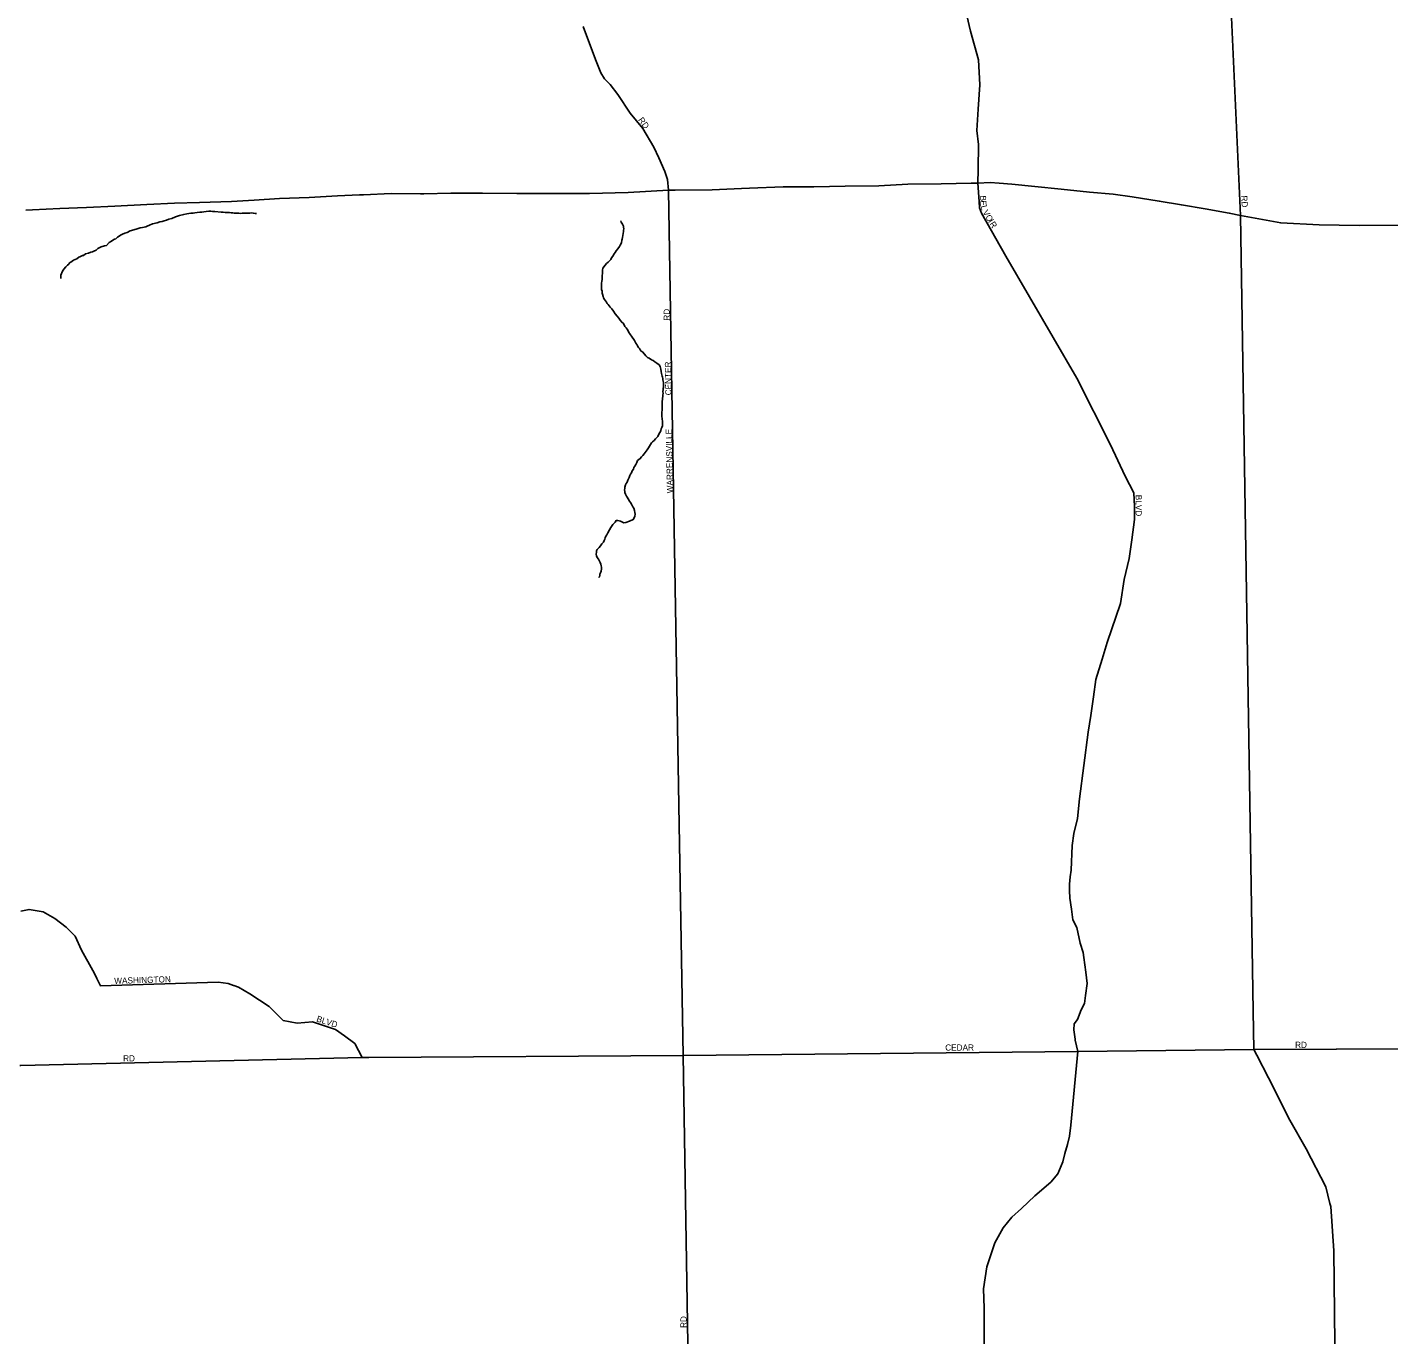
# Model space of a CAD drawing. Extents: x 2139079 to 2262683, y 1235796 to 1334992.
# Drawn here: x 2227269 to 2238345, y 1274636 to 1285350 of the extents above; entities that cross this region are included whole.
import ezdxf

# ---------------------------------------------------------------- set-up
doc = ezdxf.new("R2010")
doc.units = 0
for name, color, linetype in [('GM_X_City_Street', 7, 'Continuous'), ('GM_X_City_Street_Text', 7, 'Continuous'), ('GM_X_Minor_River', 7, 'Continuous'), ('GM_X_US_Route', 7, 'Continuous')]:
    doc.layers.add(name, color=color, linetype=linetype)

msp = doc.modelspace()

# ---------------------------------------------------------------- linework, layer by layer
at = {"layer": 'GM_X_City_Street'}
msp.add_line((2232642, 1274636), (2232605, 1276982), dxfattribs=at)
for points in [[(2237139, 1283818), (2237014, 1286565), (2236915, 1287904), (2236899, 1288052), (2236904, 1288072), (2236952, 1288095), (2237028, 1288171), (2237100, 1288250), (2237206, 1288419), (2237198, 1288487), (2237162, 1288590), (2237128, 1288654), (2237062, 1288738), (2236872, 1288918), (2236470, 1289275), (2235905, 1289793), (2235277, 1290427), (2232536, 1293112)], [(2232486, 1284023), (2232477, 1284111), (2232457, 1284177), (2232408, 1284288), (2232366, 1284375), (2232278, 1284526), (2232174, 1284651), (2232074, 1284803), (2232012, 1284884), (2231965, 1284931), (2231935, 1284980), (2231891, 1285086), (2231793, 1285356)], [(2234913, 1285445), (2234942, 1285319), (2235009, 1285084), (2235018, 1284880), (2235005, 1284683), (2234995, 1284510), (2235008, 1284396), (2235006, 1284191), (2235003, 1284081), (2235012, 1283932), (2235016, 1283880), (2235031, 1283836), (2235230, 1283488), (2235807, 1282493), (2236082, 1281952), (2236201, 1281696), (2236271, 1281562), (2236278, 1281450), (2236278, 1281343), (2236255, 1281178), (2236234, 1281027), (2236193, 1280855), (2236164, 1280660), (2236054, 1280342), (2236013, 1280206), (2235963, 1280042), (2235943, 1279901), (2235921, 1279748), (2235900, 1279613), (2235828, 1279071), (2235812, 1278912), (2235783, 1278789), (2235771, 1278692), (2235761, 1278491), (2235754, 1278437), (2235749, 1278377), (2235747, 1278326), (2235752, 1278262), (2235765, 1278172), (2235775, 1278086), (2235807, 1278023), (2235836, 1277897), (2235860, 1277819), (2235865, 1277779), (2235880, 1277661), (2235893, 1277567), (2235877, 1277471), (2235869, 1277404), (2235844, 1277353), (2235814, 1277274), (2235787, 1277241), (2235784, 1277191), (2235793, 1277116)], [(2232505, 1282876), (2232486, 1284023)], [(2237243, 1277344), (2237243, 1277344), (2237139, 1283818)], [(2232573, 1278860), (2232505, 1282876), (2232505, 1282876)], [(2232600, 1277295), (2232573, 1278860), (2232573, 1278860)], [(2227217, 1278156), (2227285, 1278171), (2227399, 1278150), (2227493, 1278098), (2227586, 1278026), (2227659, 1277953), (2227711, 1277839), (2227804, 1277673), (2227835, 1277611)], [(2227835, 1277611), (2227835, 1277610), (2227866, 1277548), (2228822, 1277579), (2228905, 1277568), (2228947, 1277552)], [(2228947, 1277552), (2228949, 1277552), (2228988, 1277537), (2229081, 1277485), (2229237, 1277381), (2229351, 1277267), (2229466, 1277246), (2229590, 1277256), (2229777, 1277194), (2229850, 1277142), (2229933, 1277080), (2229995, 1276965)], [(2232605, 1276982), (2232600, 1277295), (2232600, 1277295)], [(2237272, 1276984), (2237248, 1277030), (2237243, 1277344)], [(2235793, 1277116), (2235794, 1277112), (2235794, 1277107), (2235815, 1277015), (2235758, 1276416), (2235749, 1276325), (2235733, 1276259), (2235711, 1276184), (2235693, 1276117), (2235654, 1276019), (2235596, 1275951), (2235465, 1275840), (2235358, 1275736), (2235280, 1275666), (2235209, 1275579), (2235140, 1275458), (2235076, 1275263), (2235048, 1275082), (2235053, 1274925), (2235053, 1274711), (2235054, 1274636)], [(2237921, 1277033), (2239464, 1277041), (2239474, 1277041)], [(2227208, 1276902), (2227218, 1276902), (2229995, 1276965), (2230047, 1276966), (2230047, 1276966)], [(2230047, 1276966), (2232605, 1276982)], [(2232605, 1276982), (2235815, 1277015), (2237248, 1277030), (2237918, 1277033), (2237921, 1277033)], [(2237366, 1276799), (2237272, 1276984), (2237272, 1276984)], [(2237867, 1275777), (2237867, 1275777), (2237833, 1275912), (2237672, 1276222), (2237541, 1276456), (2237366, 1276799), (2237366, 1276799)], [(2237906, 1274636), (2237899, 1275392), (2237874, 1275752), (2237867, 1275777)]]:
    msp.add_lwpolyline(points, dxfattribs=at)
at = {"layer": 'GM_X_Minor_River'}
for points in [[(2227543, 1283304), (2227543, 1283318), (2227544, 1283333), (2227556, 1283365), (2227568, 1283381), (2227583, 1283400), (2227597, 1283414), (2227607, 1283422), (2227613, 1283432), (2227625, 1283439), (2227646, 1283453), (2227658, 1283459), (2227674, 1283466), (2227688, 1283478), (2227698, 1283482), (2227708, 1283486), (2227718, 1283491), (2227728, 1283493), (2227744, 1283505), (2227768, 1283510), (2227788, 1283520), (2227800, 1283522), (2227812, 1283527), (2227829, 1283535), (2227845, 1283549), (2227871, 1283562), (2227897, 1283570), (2227913, 1283573), (2227935, 1283599), (2227956, 1283608), (2227966, 1283616), (2227978, 1283624), (2227990, 1283628), (2228004, 1283641), (2228016, 1283649), (2228028, 1283657), (2228044, 1283666), (2228064, 1283674), (2228082, 1283680), (2228107, 1283693), (2228137, 1283702), (2228163, 1283710), (2228189, 1283717), (2228207, 1283719), (2228221, 1283723), (2228233, 1283726), (2228245, 1283732), (2228263, 1283738), (2228289, 1283751), (2228327, 1283759), (2228349, 1283766), (2228367, 1283768), (2228383, 1283775), (2228401, 1283779), (2228421, 1283787), (2228445, 1283794), (2228475, 1283807), (2228508, 1283817), (2228542, 1283826), (2228568, 1283832), (2228600, 1283837), (2228618, 1283837), (2228634, 1283840), (2228652, 1283842), (2228673, 1283845), (2228689, 1283845), (2228707, 1283847), (2228725, 1283850), (2228747, 1283852), (2228763, 1283852), (2228777, 1283851), (2228795, 1283851), (2228847, 1283846), (2228863, 1283844), (2228879, 1283842), (2228897, 1283841), (2228914, 1283841), (2228928, 1283839), (2228942, 1283840), (2228954, 1283838), (2228966, 1283838), (2228976, 1283838), (2228990, 1283837), (2229008, 1283835), (2229018, 1283837), (2229032, 1283837), (2229056, 1283836), (2229080, 1283838), (2229096, 1283839), (2229108, 1283837), (2229125, 1283833), (2229135, 1283833)], [(2232098, 1283774), (2232100, 1283764), (2232112, 1283746), (2232119, 1283732), (2232121, 1283722), (2232123, 1283708), (2232121, 1283698), (2232119, 1283688), (2232118, 1283672), (2232114, 1283654), (2232112, 1283638), (2232109, 1283626), (2232107, 1283616), (2232103, 1283595), (2232094, 1283577), (2232088, 1283565), (2232074, 1283547), (2232060, 1283530), (2232053, 1283518), (2232045, 1283506), (2232033, 1283488), (2232021, 1283473), (2232016, 1283459), (2232004, 1283447), (2231994, 1283439), (2231982, 1283428), (2231970, 1283414), (2231953, 1283388), (2231949, 1283374), (2231948, 1283353), (2231948, 1283343), (2231946, 1283331), (2231946, 1283321), (2231946, 1283309), (2231947, 1283299), (2231943, 1283281), (2231941, 1283269), (2231942, 1283253), (2231942, 1283241), (2231942, 1283229), (2231942, 1283215), (2231945, 1283201), (2231947, 1283187), (2231949, 1283177), (2231954, 1283159), (2231958, 1283147), (2231966, 1283133), (2231974, 1283123), (2231981, 1283113), (2231987, 1283103), (2231995, 1283093), (2232003, 1283083), (2232011, 1283073), (2232026, 1283058), (2232038, 1283038), (2232053, 1283018), (2232069, 1282998), (2232082, 1282982), (2232094, 1282965), (2232106, 1282949), (2232117, 1282941), (2232125, 1282927), (2232131, 1282915), (2232141, 1282905), (2232150, 1282893), (2232160, 1282875), (2232164, 1282865), (2232171, 1282854), (2232191, 1282828), (2232204, 1282810), (2232210, 1282800), (2232214, 1282790), (2232220, 1282778), (2232229, 1282768), (2232235, 1282758), (2232243, 1282744), (2232249, 1282735), (2232256, 1282725), (2232264, 1282715), (2232274, 1282707), (2232290, 1282689), (2232301, 1282677), (2232315, 1282663), (2232329, 1282656), (2232348, 1282642), (2232360, 1282638), (2232376, 1282628), (2232392, 1282617), (2232409, 1282603), (2232419, 1282589), (2232423, 1282567), (2232426, 1282549), (2232428, 1282533), (2232432, 1282521), (2232435, 1282511), (2232437, 1282501), (2232439, 1282491), (2232441, 1282481), (2232443, 1282471), (2232446, 1282459), (2232446, 1282449)], [(2232446, 1282449), (2232445, 1282419), (2232443, 1282409), (2232443, 1282399), (2232441, 1282385), (2232442, 1282369), (2232440, 1282359), (2232440, 1282344), (2232438, 1282332), (2232436, 1282320), (2232435, 1282306), (2232435, 1282288), (2232434, 1282266), (2232434, 1282238), (2232433, 1282212), (2232431, 1282186), (2232434, 1282162), (2232436, 1282142), (2232436, 1282125), (2232437, 1282107), (2232431, 1282093), (2232427, 1282081), (2232424, 1282069), (2232420, 1282059), (2232410, 1282043), (2232398, 1282020), (2232381, 1282000), (2232369, 1281988), (2232357, 1281977), (2232347, 1281969), (2232340, 1281955), (2232324, 1281926), (2232312, 1281912), (2232304, 1281900), (2232297, 1281890), (2232287, 1281877), (2232277, 1281865), (2232267, 1281853), (2232256, 1281839), (2232234, 1281824), (2232228, 1281808), (2232220, 1281792), (2232211, 1281778), (2232205, 1281767), (2232201, 1281753), (2232191, 1281739), (2232184, 1281725), (2232178, 1281713), (2232172, 1281701), (2232166, 1281686), (2232161, 1281674), (2232155, 1281664), (2232149, 1281648), (2232141, 1281636), (2232135, 1281625), (2232130, 1281607), (2232130, 1281597), (2232128, 1281585), (2232130, 1281573), (2232131, 1281563), (2232137, 1281549), (2232145, 1281535), (2232149, 1281525), (2232158, 1281513), (2232170, 1281494), (2232176, 1281482), (2232185, 1281470), (2232191, 1281458), (2232197, 1281448), (2232204, 1281436), (2232208, 1281418), (2232212, 1281402), (2232215, 1281386), (2232213, 1281372), (2232207, 1281358), (2232199, 1281343), (2232168, 1281329), (2232138, 1281320), (2232122, 1281318), (2232107, 1281324), (2232095, 1281329), (2232075, 1281335), (2232059, 1281335), (2232053, 1281323), (2232041, 1281312), (2232032, 1281304), (2232018, 1281280), (2232006, 1281261), (2231993, 1281235), (2231983, 1281219), (2231977, 1281207), (2231971, 1281196), (2231968, 1281184), (2231962, 1281174), (2231956, 1281160), (2231944, 1281146), (2231933, 1281129), (2231921, 1281115), (2231907, 1281099), (2231901, 1281089), (2231900, 1281079)], [(2231900, 1281079), (2231898, 1281062), (2231900, 1281048), (2231906, 1281034), (2231917, 1281021), (2231923, 1281009), (2231929, 1280993), (2231936, 1280981), (2231938, 1280967), (2231942, 1280957), (2231942, 1280943), (2231939, 1280923), (2231933, 1280910), (2231927, 1280898), (2231926, 1280888), (2231924, 1280878), (2231920, 1280874), (2231922, 1280874)]]:
    msp.add_lwpolyline(points, dxfattribs=at)
at = {"layer": 'GM_X_US_Route'}
for points in [[(2230495, 1283994), (2230716, 1284000), (2230973, 1284000), (2231251, 1283998), (2231542, 1283996), (2231806, 1283998), (2231843, 1283998), (2232157, 1284006), (2232486, 1284023)], [(2232486, 1284023), (2232539, 1284024), (2232841, 1284028), (2233081, 1284037)], [(2233081, 1284037), (2233145, 1284040), (2233418, 1284050), (2233668, 1284052), (2233923, 1284056), (2234197, 1284060), (2234432, 1284072), (2234703, 1284076), (2234949, 1284080), (2235003, 1284081), (2235103, 1284085), (2235176, 1284081), (2235280, 1284074), (2235466, 1284053), (2235681, 1284031), (2235910, 1284007), (2236104, 1283992), (2236259, 1283969), (2236478, 1283935), (2236658, 1283904), (2236851, 1283871), (2237048, 1283837), (2237139, 1283818), (2237466, 1283758), (2237778, 1283742), (2238103, 1283736), (2238544, 1283739)], [(2227313, 1283864), (2227534, 1283876), (2227752, 1283883), (2227983, 1283895), (2228241, 1283907), (2228468, 1283917), (2228670, 1283924), (2228930, 1283932), (2229115, 1283942), (2229321, 1283955), (2229564, 1283965), (2229794, 1283979), (2229973, 1283985), (2230004, 1283986), (2230231, 1283998), (2230469, 1283994), (2230495, 1283994)], [(2227259, 1283862), (2227313, 1283864)]]:
    msp.add_lwpolyline(points, dxfattribs=at)

# ---------------------------------------------------------------- texts
at = {"layer": 'GM_X_City_Street_Text'}
for s, rotation, p in [('RD', 306.2494, (2232236, 1284595)), ('B', 273.3294, (2235019, 1283979)), ('E', 273.3344, (2235021, 1283939)), ('RD', 273.011, (2237144, 1283979)), ('L', 283.6306, (2235025, 1283894)), ('V', 300.0262, (2235039, 1283845)), ('O', 301.1228, (2235061, 1283806)), ('I', 301.2083, (2235084, 1283769)), ('R', 301.2346, (2235095, 1283750)), ('RD', 90, (2232496, 1282962)), ('CENTER', 90.8947, (2232510, 1282355)), ('WARRENSVILLE', 91.0604, (2232523, 1281558)), ('BLVD', 270, (2236286, 1281545)), ('WASHINGTON', 1.8269, (2227978, 1277564)), ('BLVD', 342.0288, (2229618, 1277260)), ('CEDAR', 0, (2234737, 1277022)), ('RD', 0, (2237583, 1277044)), ('RD', 0, (2228049, 1276934)), ('RD', 90, (2232633, 1274765))]:
    msp.add_text(s, height=50, rotation=rotation, dxfattribs=at).set_placement(p)

doc.saveas('drawing.dxf')
